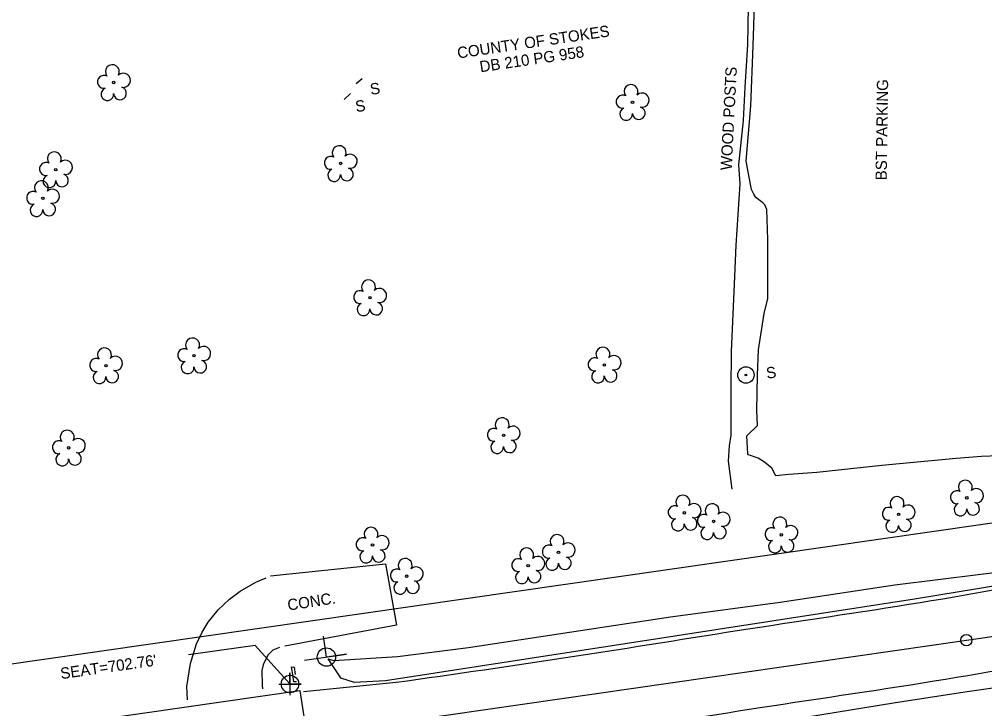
# Model space of a CAD drawing. Extents: x 1645945 to 2447332, y 713118 to 970361.
# Drawn here: x 1646888.7 to 1647146.3, y 969536.8 to 969720.6 of the extents above; entities that cross this region are included whole.
import ezdxf

# ---------------------------------------------------------------- set-up
doc = ezdxf.new("R2010")
doc.units = 0
for name, color, linetype in [('Exist Horizontal Alignment', 7, 'Continuous'), ('Exist Horizontal Alignment Station Label', 7, 'Continuous'), ('Exist Other Culture Area Outline', 7, 'Continuous'), ('Exist Other Culture Area Outline Text', 7, 'Continuous'), ('Exist Other Culture Fence Line', 7, 'Continuous'), ('Exist Other Culture Fence Line Text', 7, 'Continuous'), ('Exist Other Culture Located Object CELL', 7, 'Continuous'), ('Exist Other Culture Located Object Text', 7, 'Continuous'), ('Exist Other Culture Sign CELL', 7, 'Continuous'), ('Exist Other Culture Sign Text', 7, 'Continuous'), ('Exist Property Deed Book Text', 7, 'Continuous'), ('Exist Property Owner Text', 7, 'Continuous'), ('Exist Right of Way Line', 7, 'Continuous'), ('Exist Roads EOP', 7, 'Continuous'), ('Exist Roads EOP Other', 7, 'Continuous'), ('Exist Roads EOP Other Text', 7, 'Continuous'), ('Exist Structure Major Bridge Seat Cogo Point CELL', 7, 'Continuous'), ('Exist Structure Major Bridge Seat Leader', 7, 'Continuous'), ('Exist Structure Major Bridge Seat Top Elevation', 7, 'Continuous'), ('Exist Structure Major Bridge WW', 7, 'Continuous'), ('Exist Structure Major Deck Tunnel Box Culvert', 7, 'Continuous'), ('Exist Utilities Power Joint Use Telephone CELL', 7, 'Continuous'), ('Exist Utilities Sanitary Sewer Forced Main SUE LOS B', 7, 'Continuous'), ('Exist Utilities Telephone UG Conduit SUE LOS B', 7, 'Continuous'), ('Exist Utilities Telephone UG FO SUE LOS C', 7, 'Continuous'), ('Exist Vegetation Tree CELL', 7, 'Continuous')]:
    doc.layers.add(name, color=color, linetype=linetype)

msp = doc.modelspace()

# ---------------------------------------------------------------- linework, layer by layer
at = {"layer": 'Exist Horizontal Alignment'}
msp.add_line((1646298.92, 969433.93), (1647141.43, 969555.05), dxfattribs=at)
msp.add_arc((1647013.36, 970445.89), 900, 278.18107, 298.87121, dxfattribs=at)
at = {"layer": 'Exist Horizontal Alignment Station Label'}
msp.add_circle((1647141.43, 969555.05), 1.5, dxfattribs=at)
at = {"layer": 'Exist Other Culture Area Outline'}
for points in [[(1646955.8, 969572.18), (1646986.42, 969575.44), (1646989.4, 969559.08), (1646959.61, 969553.44)], [(1646933.57, 969539.17), (1646933.43, 969542.71), (1646934.43, 969548.85), (1646936, 969554.12), (1646937.55, 969557.22), (1646939.11, 969559.87), (1646941.75, 969563.13), (1646944.79, 969566.03), (1646947.63, 969568.1), (1646951.87, 969570.55), (1646954.64, 969571.64)], [(1646958.13, 969553.09), (1646956.42, 969552.39), (1646955.09, 969551.02), (1646953.78, 969548.51), (1646953.44, 969546.93), (1646953.54, 969543.07), (1646953.63, 969542.11)]]:
    msp.add_lwpolyline(points, dxfattribs=at)
at = {"layer": 'Exist Other Culture Fence Line'}
msp.add_lwpolyline([(1647078.92, 969595.31), (1647077.99, 969602.76), (1647078.22, 969606.83), (1647078.64, 969609.7), (1647078.71, 969621.89), (1647078.74, 969632), (1647079.62, 969652.03), (1647079.98, 969660.39), (1647081.07, 969676.73), (1647080.72, 969681.8), (1647081.99, 969693.61), (1647082.44, 969702.47), (1647083.15, 969713.81), (1647083.54, 969739.31), (1647084.38, 969747.38), (1647084.92, 969760.21), (1647085.61, 969776.92)], dxfattribs=at)
at = {"layer": 'Exist Other Culture Located Object CELL'}
for radius in [2.18, 0.24]:
    msp.add_circle((1647082.62, 969625.76), radius, dxfattribs=at)
at = {"layer": 'Exist Other Culture Sign CELL'}
for p, q in [((1646980.2, 969704.71), (1646978.65, 969703.39)), ((1646977.12, 969700.79), (1646975.4, 969699.19))]:
    msp.add_line(p, q, dxfattribs=at)
at = {"layer": 'Exist Right of Way Line'}
msp.add_line((1646341.77, 969470.4), (1647145.86, 969586), dxfattribs=at)
msp.add_arc((1647025.62, 970422.4), 845, 278.18107, 299.46236, dxfattribs=at)
at = {"layer": 'Exist Roads EOP'}
msp.add_line((1646989.26, 969543.73), (1646964.55, 969541.26), dxfattribs=at)
for points in [[(1647712.71, 969946.05), (1647689.83, 969906.56), (1647665.85, 969869.13), (1647637.34, 969829.12), (1647607.92, 969794.57), (1647574.53, 969760.72), (1647538.69, 969730.5), (1647499.85, 969702.79), (1647457.34, 969676.33), (1647411.66, 969651.37), (1647366.8, 969630.41), (1647321.37, 969611.83), (1647279.28, 969597.97), (1647224.82, 969583.15), (1647179.92, 969574.15), (1647132.17, 969565.53), (1647083.22, 969557.97), (1647036.22, 969550.58), (1646989.26, 969543.73)], [(1647731.3, 969935.45), (1647707.71, 969895.07), (1647684.27, 969857.13), (1647654.38, 969814.5), (1647624.46, 969779.25), (1647589.97, 969744.66), (1647553.5, 969714.01), (1647512.43, 969684.95), (1647469.3, 969658.19), (1647421.26, 969632.07), (1647375.68, 969609.9), (1647329.15, 969590.49), (1647286.02, 969576.26), (1647230.19, 969561.18), (1647183.04, 969552.75), (1647135.89, 969544.58), (1647086.4, 969536.99), (1647040.14, 969529.53), (1646992.05, 969522.32)]]:
    msp.add_spline(points, degree=3, dxfattribs=at)
at = {"layer": 'Exist Roads EOP Other'}
msp.add_lwpolyline([(1647152.28, 969604.27), (1647145.5, 969604.01), (1647138.68, 969603.52), (1647118.85, 969601.62), (1647101.55, 969599.79), (1647094.07, 969599.24), (1647090.59, 969598.89), (1647089.51, 969600.96), (1647087.59, 969602.53), (1647085.86, 969603.56), (1647083.33, 969604.44), (1647083.15, 969604.76), (1647082.82, 969609.55), (1647085.72, 969612.33), (1647085.52, 969616.27), (1647085.74, 969625.69), (1647085.97, 969632.47), (1647087.47, 969642.15), (1647088.42, 969646.17), (1647088.43, 969653.44), (1647088.48, 969661.9), (1647088.15, 969669.9), (1647087.68, 969671.16), (1647087.14, 969671.64), (1647085.24, 969673.07), (1647084.75, 969673.95), (1647084.12, 969675.25), (1647082.66, 969682.79), (1647083.93, 969697.56), (1647084.58, 969713.54), (1647084.93, 969724.35)], dxfattribs=at)
at = {"layer": 'Exist Structure Major Bridge Seat Cogo Point CELL'}
msp.add_lwpolyline([(1646957.95, 969543.35), (1646963.95, 969543.35), (1646960.95, 969543.35), (1646960.95, 969546.35), (1646960.95, 969540.35)], dxfattribs=at)
msp.add_circle((1646960.95, 969543.35), 2.34, dxfattribs=at)
at = {"layer": 'Exist Structure Major Bridge Seat Leader'}
msp.add_lwpolyline([(1646960.94, 969543.42), (1646951.69, 969553.66), (1646933.91, 969551.12)], dxfattribs=at)
at = {"layer": 'Exist Structure Major Bridge WW'}
msp.add_lwpolyline([(1646962.72, 969543.97), (1646962.02, 969543.94), (1646961.71, 969545.78), (1646961.34, 969547.9), (1646962.11, 969547.81), (1646962.32, 969545.86)], dxfattribs=at)
at = {"layer": 'Exist Structure Major Deck Tunnel Box Culvert'}
msp.add_lwpolyline([(1646967.24, 969517.89), (1646619.97, 969468.05), (1646615.96, 969491.55), (1646963.57, 969541.6), (1646967.24, 969517.89)], dxfattribs=at)
at = {"layer": 'Exist Utilities Power Joint Use Telephone CELL'}
msp.add_line((1646970.69, 969550.55), (1646970.69, 969550.55), dxfattribs=at)
msp.add_lwpolyline([(1646964.82, 969549.7), (1646976.04, 969551.28), (1646970.7, 969550.53), (1646969.89, 969556.12)], dxfattribs=at)
msp.add_circle((1646970.69, 969550.56), 2.45, dxfattribs=at)
at = {"layer": 'Exist Utilities Sanitary Sewer Forced Main SUE LOS B'}
msp.add_lwpolyline([(1646968.01, 969517.18), (1647007.02, 969521.34), (1647054.78, 969528.26), (1647083.72, 969532.15), (1647121.99, 969538.31), (1647141.01, 969541.29), (1647166.59, 969544.9), (1647192.95, 969550.61), (1647220.41, 969556.52), (1647247.21, 969563.1), (1647258.95, 969564.71), (1647268.16, 969566.61), (1647282, 969570.9)], dxfattribs=at)
at = {"layer": 'Exist Utilities Telephone UG Conduit SUE LOS B'}
msp.add_lwpolyline([(1646971.06, 969550.08), (1646972.68, 969549.64), (1646989.64, 969550.72), (1647008.61, 969553.11), (1647062.47, 969561.3), (1647091.71, 969565.17), (1647122.37, 969569.84), (1647156.76, 969574.05), (1647161.18, 969573.8), (1647163.08, 969572.94), (1647166.01, 969571.06), (1647172.25, 969572.15), (1647180.09, 969572.82), (1647225.19, 969575.03), (1647241.94, 969576.58), (1647256.28, 969578.26), (1647280.32, 969579.71), (1647288.53, 969579.4)], dxfattribs=at)
at = {"layer": 'Exist Utilities Telephone UG FO SUE LOS C'}
msp.add_lwpolyline([(1646971.06, 969550.08), (1646974.44, 969544.99), (1646978.11, 969543.87), (1646986.45, 969544.32), (1647127.62, 969566.11), (1647174.71, 969573.78), (1647223.48, 969584.86), (1647255.93, 969594.24), (1647291.19, 969605.96)], dxfattribs=at)
at = {"layer": 'Exist Vegetation Tree CELL'}
for p, q in [((1646913.94, 969703.76), (1646913.94, 969703.76)), ((1647052.35, 969698.47), (1647052.35, 969698.47)), ((1646898.47, 969680.54), (1646898.47, 969680.54)), ((1646974.46, 969682.17), (1646974.46, 969682.17)), ((1646895.02, 969672.84), (1646895.02, 969672.84)), ((1646982.29, 969646.37), (1646982.29, 969646.37)), ((1646935.34, 969630.9), (1646935.34, 969630.9)), ((1646911.84, 969628.26), (1646911.84, 969628.26)), ((1647044.85, 969628.44), (1647044.85, 969628.44)), ((1647017.95, 969609.65), (1647017.95, 969609.65)), ((1646901.9, 969606.34), (1646901.9, 969606.34)), ((1647141.54, 969593), (1647141.54, 969593)), ((1647066.19, 969589), (1647066.19, 969589)), ((1647123.34, 969588.6), (1647123.34, 969588.6)), ((1647073.98, 969586.71), (1647073.98, 969586.71)), ((1647092.05, 969583.14), (1647092.05, 969583.14)), ((1646982.97, 969580.44), (1646982.97, 969580.44)), ((1647032.61, 969578.49), (1647032.61, 969578.49)), ((1647024.51, 969574.92), (1647024.51, 969574.92)), ((1646992.07, 969572.12), (1646992.07, 969572.12))]:
    msp.add_line(p, q, dxfattribs=at)
for centre in [(1646913.94, 969703.76), (1647052.35, 969698.47), (1646898.47, 969680.54), (1646974.46, 969682.17), (1646895.02, 969672.84), (1646982.29, 969646.37), (1646935.34, 969630.9), (1646911.84, 969628.26), (1647044.85, 969628.44), (1647017.95, 969609.65), (1646901.9, 969606.34), (1647141.54, 969593), (1647066.19, 969589), (1647123.34, 969588.6), (1647073.98, 969586.71), (1647092.05, 969583.14), (1646982.97, 969580.44), (1647032.61, 969578.49), (1647024.51, 969574.92), (1646992.07, 969572.12)]:
    msp.add_circle(centre, 0.326, dxfattribs=at)
for centre, radius, start, end in [((1646913.55, 969706.64), 1.86, 330.1651, 219.7134), ((1646916.48, 969704.35), 1.9, 257.1011, 134.1999), ((1646911.33, 969703.92), 1.73, 62.6636, 279.3457), ((1646912.23, 969700.64), 1.69, 111.5671, 6.231), ((1646915.61, 969700.86), 1.7, 181.2822, 74.56), ((1647051.96, 969701.35), 1.86, 330.1651, 219.7134), ((1647054.89, 969699.06), 1.9, 257.1011, 134.1999), ((1647049.74, 969698.63), 1.73, 62.6636, 279.3457), ((1647050.64, 969695.35), 1.69, 111.5671, 6.231), ((1647054.02, 969695.57), 1.7, 181.2822, 74.56), ((1646974.08, 969685.04), 1.86, 330.1651, 219.7134), ((1646898.08, 969683.42), 1.86, 330.1651, 219.7134), ((1646901.02, 969681.13), 1.9, 257.1011, 134.1999), ((1646971.86, 969682.32), 1.73, 62.6636, 279.3457), ((1646977.01, 969682.76), 1.9, 257.1011, 134.1999), ((1646895.86, 969680.7), 1.73, 62.6636, 279.3457), ((1646972.76, 969679.05), 1.69, 111.5671, 6.231), ((1646976.14, 969679.27), 1.7, 181.2822, 74.56), ((1646896.76, 969677.42), 1.69, 111.5671, 6.231), ((1646900.14, 969677.64), 1.7, 181.2822, 74.56), ((1646894.63, 969675.71), 1.86, 330.1651, 219.7134), ((1646897.57, 969673.43), 1.9, 257.1011, 134.1999), ((1646892.41, 969672.99), 1.73, 62.6636, 279.3457), ((1646893.32, 969669.72), 1.69, 111.5671, 6.231), ((1646896.69, 969669.94), 1.7, 181.2822, 74.56), ((1646981.9, 969649.25), 1.86, 330.1651, 219.7134), ((1646979.68, 969646.53), 1.73, 62.6636, 279.3457), ((1646984.84, 969646.96), 1.9, 257.1011, 134.1999), ((1646980.58, 969643.25), 1.69, 111.5671, 6.231), ((1646983.96, 969643.47), 1.7, 181.2822, 74.56), ((1646934.96, 969633.77), 1.86, 330.1651, 219.7134), ((1646911.45, 969631.13), 1.86, 330.1651, 219.7134), ((1646932.74, 969631.05), 1.73, 62.6636, 279.3457), ((1646937.89, 969631.49), 1.9, 257.1011, 134.1999), ((1647044.46, 969631.31), 1.86, 330.1651, 219.7134), ((1646909.23, 969628.41), 1.73, 62.6636, 279.3457), ((1646914.38, 969628.85), 1.9, 257.1011, 134.1999), ((1646933.64, 969627.78), 1.69, 111.5671, 6.231), ((1646937.02, 969628), 1.7, 181.2822, 74.56), ((1647042.24, 969628.59), 1.73, 62.6636, 279.3457), ((1647047.4, 969629.03), 1.9, 257.1011, 134.1999), ((1646910.13, 969625.14), 1.69, 111.5671, 6.231), ((1646913.51, 969625.36), 1.7, 181.2822, 74.56), ((1647043.14, 969625.32), 1.69, 111.5671, 6.231), ((1647046.52, 969625.54), 1.7, 181.2822, 74.56), ((1647017.56, 969612.52), 1.86, 330.1651, 219.7134), ((1646901.51, 969609.21), 1.86, 330.1651, 219.7134), ((1647015.34, 969609.8), 1.73, 62.6636, 279.3457), ((1647020.49, 969610.24), 1.9, 257.1011, 134.1999), ((1646904.45, 969606.93), 1.9, 257.1011, 134.1999), ((1647019.62, 969606.75), 1.7, 181.2822, 74.56), ((1646899.29, 969606.49), 1.73, 62.6636, 279.3457), ((1647016.24, 969606.53), 1.69, 111.5671, 6.231), ((1646900.2, 969603.22), 1.69, 111.5671, 6.231), ((1646903.57, 969603.44), 1.7, 181.2822, 74.56), ((1647141.16, 969595.88), 1.86, 330.1651, 219.7134), ((1647144.09, 969593.59), 1.9, 257.1011, 134.1999), ((1647065.8, 969591.87), 1.86, 330.1651, 219.7134), ((1647122.95, 969591.47), 1.86, 330.1651, 219.7134), ((1647138.94, 969593.16), 1.73, 62.6636, 279.3457), ((1647063.58, 969589.15), 1.73, 62.6636, 279.3457), ((1647068.74, 969589.59), 1.9, 257.1011, 134.1999), ((1647073.59, 969589.58), 1.86, 330.1651, 219.7134), ((1647120.73, 969588.76), 1.73, 62.6636, 279.3457), ((1647125.88, 969589.19), 1.9, 257.1011, 134.1999), ((1647139.84, 969589.88), 1.69, 111.5671, 6.231), ((1647143.22, 969590.1), 1.7, 181.2822, 74.56), ((1647067.86, 969586.1), 1.7, 181.2822, 74.56), ((1647071.37, 969586.86), 1.73, 62.6636, 279.3457), ((1647076.53, 969587.3), 1.9, 257.1011, 134.1999), ((1647091.66, 969586.02), 1.86, 330.1651, 219.7134), ((1646982.59, 969583.31), 1.86, 330.1651, 219.7134), ((1647064.48, 969585.88), 1.69, 111.5671, 6.231), ((1647072.27, 969583.59), 1.69, 111.5671, 6.231), ((1647075.65, 969583.81), 1.7, 181.2822, 74.56), ((1647094.59, 969583.73), 1.9, 257.1011, 134.1999), ((1647121.63, 969585.48), 1.69, 111.5671, 6.231), ((1647125.01, 969585.7), 1.7, 181.2822, 74.56), ((1646985.52, 969581.03), 1.9, 257.1011, 134.1999), ((1647032.23, 969581.36), 1.86, 330.1651, 219.7134), ((1647089.44, 969583.3), 1.73, 62.6636, 279.3457), ((1646980.36, 969580.59), 1.73, 62.6636, 279.3457), ((1647030, 969578.64), 1.73, 62.6636, 279.3457), ((1647035.16, 969579.08), 1.9, 257.1011, 134.1999), ((1647090.34, 969580.02), 1.69, 111.5671, 6.231), ((1647093.72, 969580.24), 1.7, 181.2822, 74.56), ((1646981.27, 969577.32), 1.69, 111.5671, 6.231), ((1646984.64, 969577.54), 1.7, 181.2822, 74.56), ((1647024.12, 969577.79), 1.86, 330.1651, 219.7134), ((1647027.06, 969575.51), 1.9, 257.1011, 134.1999), ((1646991.68, 969575), 1.86, 330.1651, 219.7134), ((1647021.9, 969575.07), 1.73, 62.6636, 279.3457), ((1647030.91, 969575.37), 1.69, 111.5671, 6.231), ((1647034.28, 969575.59), 1.7, 181.2822, 74.56), ((1646989.46, 969572.28), 1.73, 62.6636, 279.3457), ((1646994.62, 969572.71), 1.9, 257.1011, 134.1999), ((1647022.81, 969571.8), 1.69, 111.5671, 6.231), ((1647026.18, 969572.02), 1.7, 181.2822, 74.56), ((1646990.36, 969569), 1.69, 111.5671, 6.231), ((1646993.74, 969569.22), 1.7, 181.2822, 74.56)]:
    msp.add_arc(centre, radius, start, end, dxfattribs=at)

# ---------------------------------------------------------------- texts
at = {"layer": 'Exist Other Culture Area Outline Text'}
msp.add_text('CONC.', height=3, rotation=8.7749, dxfattribs=at).set_placement((1646960.52, 969562.91))
at = {"layer": 'Exist Other Culture Fence Line Text'}
msp.add_text('WOOD POSTS', height=3, rotation=87.0956, dxfattribs=at).set_placement((1647078.81, 969680.29))
at = {"layer": 'Exist Other Culture Located Object Text'}
msp.add_text('S', height=3, rotation=8.7749, dxfattribs=at).set_placement((1647088.25, 969624.73))
at = {"layer": 'Exist Other Culture Sign Text'}
for p in [(1646982.55, 969700.44), (1646978.63, 969695.83)]:
    msp.add_text('S', height=3, rotation=8.7749, dxfattribs=at).set_placement(p)
at = {"layer": 'Exist Property Deed Book Text'}
msp.add_text('DB 210 PG 958', height=3, rotation=8.3302, dxfattribs=at).set_placement((1647011.79, 969706.46))
at = {"layer": 'Exist Property Owner Text'}
msp.add_text('COUNTY OF STOKES', height=3, rotation=8.3302, dxfattribs=at).set_placement((1647005.81, 969710.13))
at = {"layer": 'Exist Roads EOP Other Text'}
msp.add_text('BST PARKING', height=3, rotation=89.1707, dxfattribs=at).set_placement((1647120.18, 969677.66))
at = {"layer": 'Exist Structure Major Bridge Seat Top Elevation'}
msp.add_text("SEAT=702.76'", height=3, rotation=8.1056, dxfattribs=at).set_placement((1646899.9, 969544.65))

doc.saveas('drawing.dxf')
